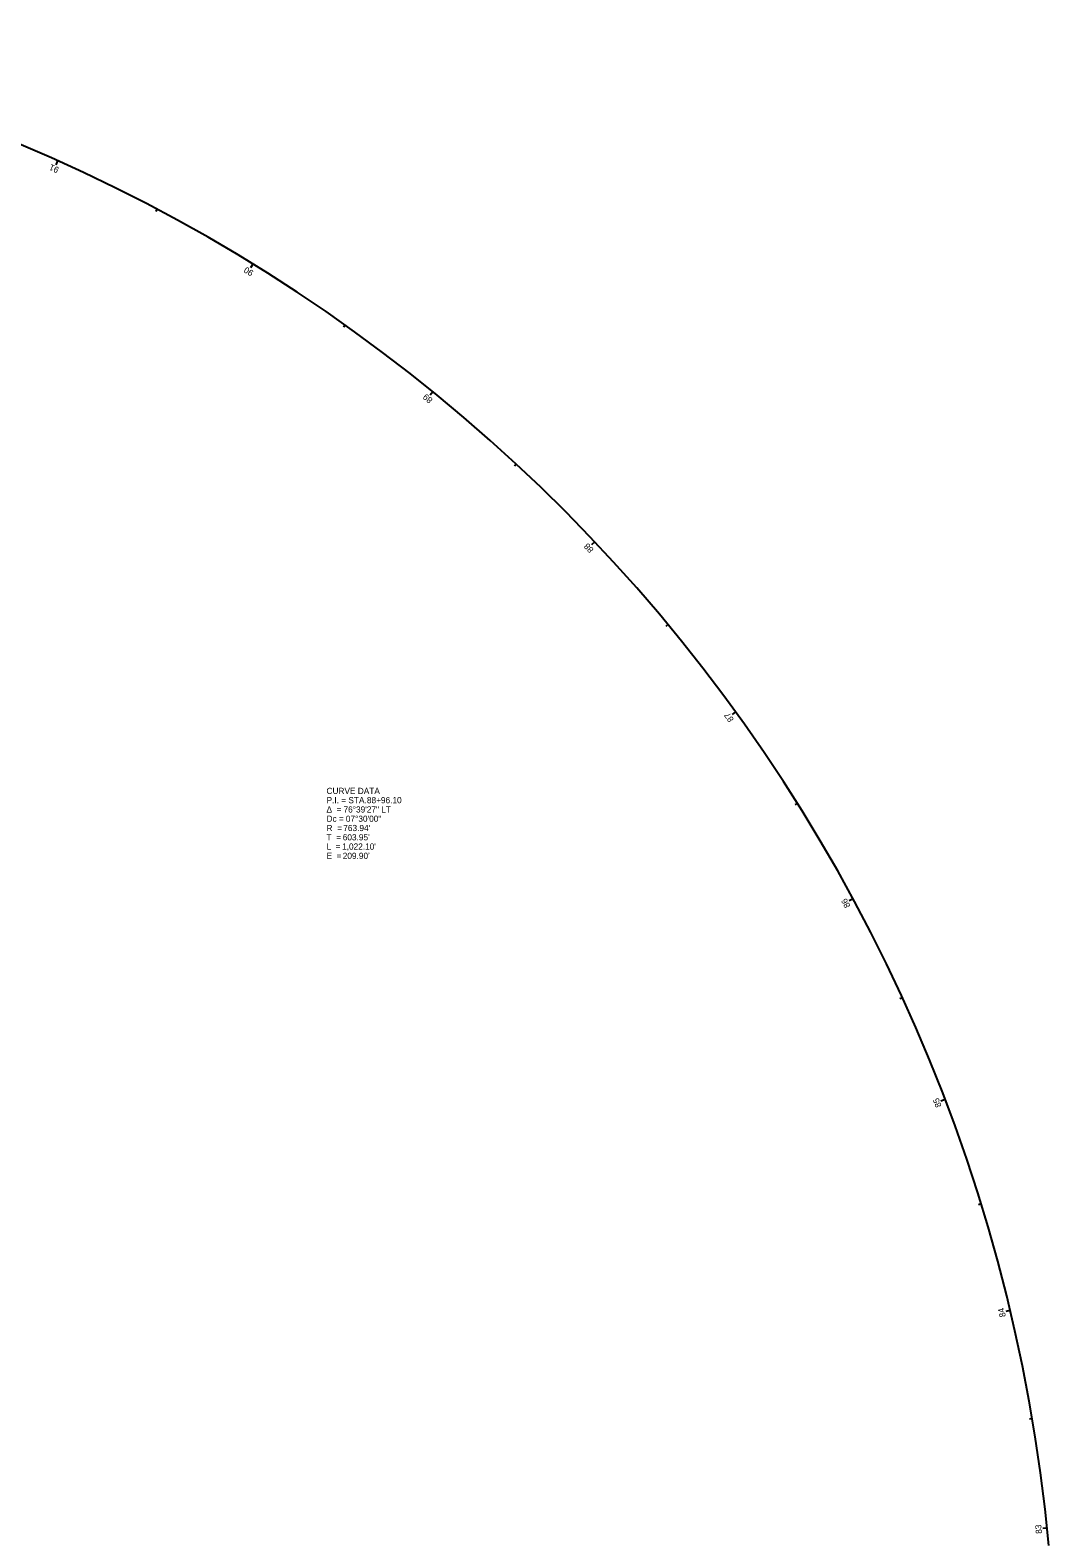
# Model space of a CAD drawing. Extents: x 2200877 to 2202699, y 632416 to 635901.
# Drawn here: x 2202232 to 2202693, y 635100 to 635782 of the extents above; entities that cross this region are included whole.
import ezdxf

# ---------------------------------------------------------------- set-up
doc = ezdxf.new("R2010")
doc.units = 0
for name, color, linetype in [('_CIVIL_CONSTRUCTION', 7, 'Continuous'), ('RW_X_CL_100_Cardinal_Points', 7, 'Continuous'), ('SH_Data', 7, 'Continuous')]:
    doc.layers.add(name, color=color, linetype=linetype)

msp = doc.modelspace()

# ---------------------------------------------------------------- linework, layer by layer
at = {"layer": 'RW_X_CL_100_Cardinal_Points'}
for p, q in [((2202244.2, 635723.13), (2202243.38, 635721.3)), ((2202289.13, 635701.22), (2202288.57, 635700.16)), ((2202332.54, 635676.42), (2202331.49, 635674.72)), ((2202374.23, 635648.84), (2202373.54, 635647.86)), ((2202414.03, 635618.58), (2202412.77, 635617.03)), ((2202451.76, 635585.79), (2202450.95, 635584.91)), ((2202487.27, 635550.61), (2202485.82, 635549.23)), ((2202520.4, 635513.17), (2202519.48, 635512.4)), ((2202551.02, 635473.65), (2202549.4, 635472.48)), ((2202578.98, 635432.21), (2202577.96, 635431.57)), ((2202604.17, 635389.03), (2202602.41, 635388.08)), ((2202626.48, 635344.29), (2202625.39, 635343.79)), ((2202645.82, 635298.2), (2202643.95, 635297.48)), ((2202662.11, 635250.93), (2202660.96, 635250.58)), ((2202675.26, 635202.7), (2202673.32, 635202.24)), ((2202685.24, 635153.72), (2202684.06, 635153.52)), ((2202691.99, 635104.18), (2202690, 635103.98))]:
    msp.add_line(p, q, dxfattribs=at)
at = {"layer": 'SH_Data'}
msp.add_arc((2201932.07, 635025.86), 763.94, 5.2962, 81.9537, dxfattribs=at)
msp.add_arc((2201932.07, 635025.86), 763.94, 5.2962, 81.9537, dxfattribs=at)

# ---------------------------------------------------------------- texts
at = {"layer": '_CIVIL_CONSTRUCTION'}
for s, p in [('CURVE DATA', (2202365.88, 635436.52)), ('Δ  = ', (2202365.88, 635428.12)), ('P.I. = STA. ', (2202365.88, 635432.32)), ('76°39\'27" LT', (2202373.56, 635428.12)), ('88+96.10', (2202384.15, 635432.32)), ('Dc = ', (2202365.88, 635423.92)), ('07°30\'00"', (2202374.62, 635423.92)), ('T  = ', (2202365.88, 635415.52)), ('R  = ', (2202365.88, 635419.72)), ("603.95'", (2202373.22, 635415.52)), ("763.94'", (2202373.46, 635419.72)), ('L  = ', (2202365.88, 635411.32)), ('E  = ', (2202365.88, 635407.12)), ("1,022.10'", (2202372.92, 635411.32)), ("209.90'", (2202373.22, 635407.12))]:
    msp.add_text(s, height=2.8, dxfattribs=at).set_placement(p)
at = {"layer": 'RW_X_CL_100_Cardinal_Points'}
for s, rotation, p in [('91', 155.88491, (2202245.03, 635720.01)), ('90', 148.38491, (2202333.13, 635673.12)), ('89', 140.88491, (2202414.16, 635615.26)), ('88', 133.38491, (2202486.98, 635547.28)), ('87', 125.88491, (2202550.34, 635470.32)), ('86', 118.38491, (2202603.04, 635385.87)), ('85', 110.88491, (2202644.27, 635295.26)), ('84', 103.38491, (2202673.33, 635200.03)), ('83', 95.88491, (2202689.72, 635101.78))]:
    msp.add_text(s, height=2.8, rotation=rotation, dxfattribs=at).set_placement(p)

doc.saveas('drawing.dxf')
